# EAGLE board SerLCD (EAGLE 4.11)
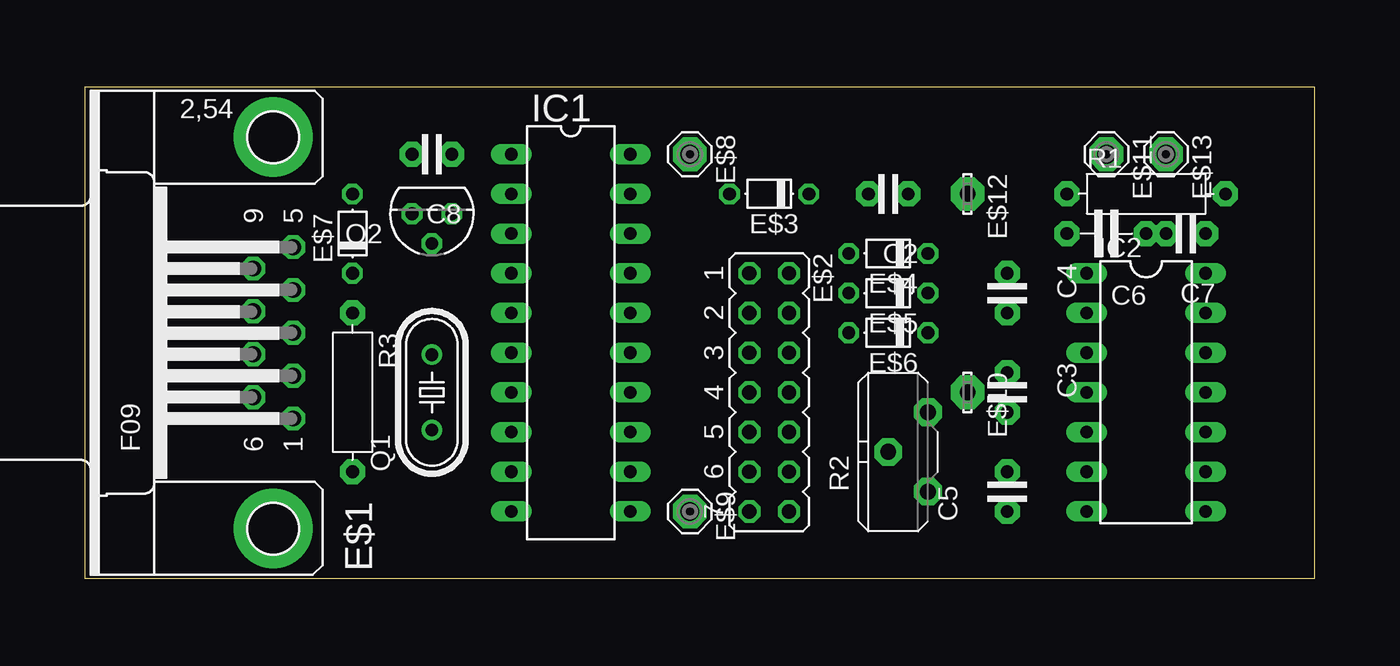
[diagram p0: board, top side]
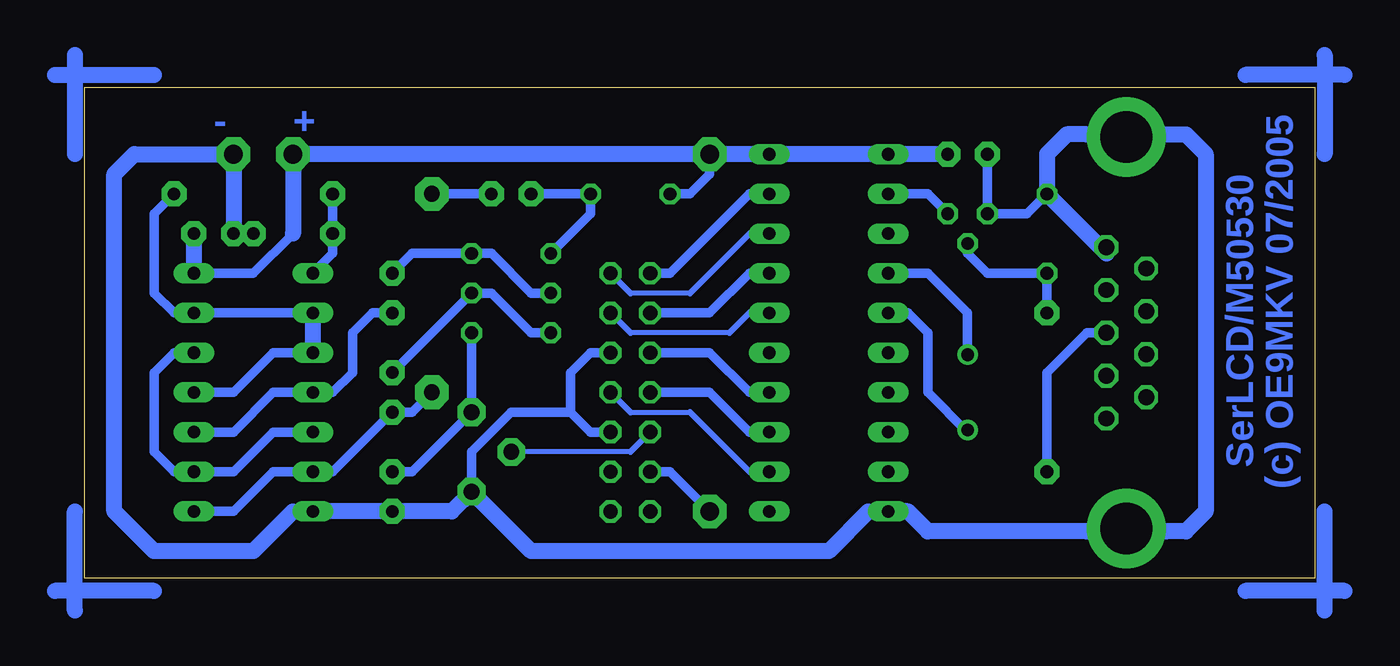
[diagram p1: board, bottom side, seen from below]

Size 78.73 x 31.42 mm. Coordinates in mm from the lower left corner, seen from the top.
Outline: 0,31.42 0,0 78.73,0 78.73,31.42 0,31.42
Copper layers (1*16): Top 0.035mm / dielectric 1.5mm / Bottom 0.035mm
Design rules "default": minimum track width 10mil, minimum drill 24mil, track to track 8mil, track to pad 8mil, pad to pad 8mil, via to via 8mil, smd to smd 8mil, copper to edge 40mil, drill to drill 8mil, minimum pad ring 10mil, minimum via ring 8mil, stop-mask expansion 4mil, vias tented up to drill 0mil, thermal gap 10mil

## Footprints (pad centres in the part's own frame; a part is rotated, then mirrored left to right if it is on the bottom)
C-2,5 = drill 0.813 pad 1.6 octagon: 1 -1.27,0; 2 1.27,0
C-5 = drill 0.813 pad 1.6 octagon: 1 -2.54,0; 2 2.54,0
F09HP = drill 1.016 octagon: 1 -5.486,-1.27; 2 -2.743,-1.27; 3 0,-1.27; 4 2.743,-1.27; 5 5.486,-1.27; 6 -4.115,1.27; 7 -1.372,1.27; 8 1.372,1.27; 9 4.115,1.27 | drill 3.302 pad 5.08 round: G1 -12.522,0; G2 12.522,0
JP7Q = drill 0.914 octagon: 1 -7.62,-1.27; 2 -7.62,1.27; 3 -5.08,-1.27; 4 -5.08,1.27; 5 -2.54,-1.27; 6 -2.54,1.27; 7 0,-1.27; 8 0,1.27; 9 2.54,-1.27; 10 2.54,1.27; 11 5.08,-1.27; 12 5.08,1.27; 13 7.62,-1.27; 14 7.62,1.27
D-5 = drill 0.813 octagon: A 2.54,0; C -2.54,0
MCS08 = drill 1.194 pad 2.159 octagon: MP 0,0
LSP10 = drill 1.016 pad 2.159 octagon: MP 0,0
DIL20 = drill 0.813 long: 1 -11.43,-3.81; 2 -8.89,-3.81; 3 -6.35,-3.81; 4 -3.81,-3.81; 5 -1.27,-3.81; 6 1.27,-3.81; 7 3.81,-3.81; 8 6.35,-3.81; 9 8.89,-3.81; 10 11.43,-3.81; 11 11.43,3.81; 12 8.89,3.81; 13 6.35,3.81; 14 3.81,3.81; 15 1.27,3.81; 16 -1.27,3.81; 17 -3.81,3.81; 18 -6.35,3.81; 19 -8.89,3.81; 20 -11.43,3.81
DIL14 = drill 0.813 long: 1 -7.62,-3.81; 2 -5.08,-3.81; 3 -2.54,-3.81; 4 0,-3.81; 5 2.54,-3.81; 6 5.08,-3.81; 7 7.62,-3.81; 8 7.62,3.81; 9 5.08,3.81; 10 2.54,3.81; 11 0,3.81; 12 -2.54,3.81; 13 -5.08,3.81; 14 -7.62,3.81
HC49/S = drill 0.813 round: 1 -2.413,0; 2 2.413,0
TO92 = drill 0.813 octagon: 1 1.27,0; 2 0,1.905; 3 -1.27,0
R-10 = drill 0.813 pad 1.6 octagon: 1 -5.08,0; 2 5.08,0
PT-10S = drill 1.016 pad 1.778 octagon: 1 -2.54,-1.27; 2 2.54,-1.27; 3 0,1.27

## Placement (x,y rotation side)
C2  10µ/16V  [C-2,5]  51.43,24.6 180 top
C3  10µ/16V  [C-2,5]  59.05,11.9 270 top
C4  10µ/16V  [C-2,5]  59.05,18.25 270 top
C5  22µ/35V  [C-2,5]  59.05,5.55 90 top
C6  1n  [C-5]  65.4,22.06 180 top
C7  100n  [C-2,5]  70.48,22.06 180 top
C8  100n  [C-2,5]  22.22,27.14 180 top
E$1  [F09HP]  12.06,15.71 90 top
E$2  [JP7Q]  43.81,11.9 270 top
E$3  [D-5]  43.81,24.6 180 top
E$4  [D-5]  51.43,20.79 180 top
E$5  [D-5]  51.43,18.25 180 top
E$6  [D-5]  51.43,15.71 180 top
E$7  [D-5]  17.14,22.06 90 top
E$8  [MCS08]  38.73,27.14 270 top
E$9  [MCS08]  38.73,4.28 270 top
E$10  [LSP10]  56.51,11.9 270 top
E$11  [MCS08]  65.4,27.14 270 top
E$12  [LSP10]  56.51,24.6 270 top
E$13  [MCS08]  69.21,27.14 270 top
IC1  AT90S2313P  [DIL20]  31.11,15.71 270 top
IC2  74HC14  [DIL14]  67.94,11.9 270 top
Q1  3.579545 MHz  [HC49/S]  22.22,11.9 90 top
Q2  BC547  [TO92]  22.22,23.33 180 top
R1  6k8  [R-10]  67.94,24.6 0 top
R2  10k  [PT-10S]  52.7,8.09 90 top
R3  10k  [R-10]  17.14,11.9 270 top

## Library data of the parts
C2-C8 R1-R3 = discrete
E$1 = con-subd
E$2 = jumper
E$3-E$7 = diode
E$8-E$13 = solpad
IC1 = atmel
IC2 = 74xx-eu
Q1 = crystal
Q2 = transistor-npn

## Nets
GND: C7.2 E$2.10 IC2.7
N$8: IC2.2 IC2.3 IC2.11 IC2.13
N$19: R2.1
N$23: C7.1 C8.1 E$3.A IC1.1 IC1.20 IC2.14
N$25: IC1.19
N$26: IC1.18
N$27: IC1.17
N$28: IC1.16
N$29: IC1.14
N$30: IC1.13
N$31: IC1.12
N$32: R2.3
N$35: R3.1
S$1: R3.2
S$2: E$1.3
S$3: Q2.3
S$5: IC2.6 IC2.8
S$6: E$2.1
S$7: E$2.3
S$8: E$2.2
S$9: E$2.4
S$10: E$2.7
S$12: E$2.8
S$14: C2.1
S$15: E$2.9
S$16: E$2.11 E$9.MP
S$18: Q2.1
S$19: E$2.6
S$21: IC2.4 IC2.10
S$24: IC2.5 IC2.9 IC2.12
S$27: C2.2 E$3.C E$4.A
S$29: IC1.4
S$30: IC1.5
S$31: R1.1
S$32: E$5.C E$6.A
S$33: C5.2 E$6.C R2.2
S$34: C4.2
S$35: C3.2 E$10.MP
S$36: E$4.C E$5.A
S$37: C4.1

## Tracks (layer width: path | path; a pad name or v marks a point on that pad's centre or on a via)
GND
  Bottom 0.61: E$2.10 46.35,9.36 47.62,10.63 | 47.62,10.63 47.62,11.9 | IC2.7 65.4,4.28 | 47.62,10.63 51.43,10.63 53.97,8.09 53.97,5.55 | 27.3,4.28 28.57,4.28
  Bottom 1.016: 65.4,4.28 67.94,1.74 74.29,1.74 76.83,4.28 76.83,25.87 75.56,27.14 69.21,27.14 C7.2 | IC2.7 55.24,4.28 53.97,5.55 50.16,1.74 31.11,1.74 28.57,4.28 | 27.3,4.28 26.03,4.28 24.76,3.01 14.6,3.01
N$8
  Bottom 0.61: IC2.11 69.21,11.9 66.67,14.44 IC2.3 | 73.02,24.6 74.29,23.33 74.29,18.25 73.02,16.98 IC2.13 IC2.2
  Bottom 1.016: IC2.2 IC2.3
N$23
  Bottom 0.61: 65.4,22.06 67.94,19.52 IC2.14 | 38.73,27.14 38.73,25.87 40,24.6 E$3.A
  Bottom 1.016: 65.4,22.06 65.4,27.14 38.73,27.14 IC1.20 IC1.1 C8.1 | C7.1 IC2.14
N$35
  Bottom 0.61: 22.22,20.79 20.95,19.52 17.14,19.52 R3.1
S$1
  Bottom 0.61: 17.14,13.17 R3.2
S$2
  Bottom 0.61: E$1.3 14.6,15.71 17.14,13.17
S$3
  Bottom 0.61: 26.03,24.6 24.76,24.6 Q2.3
S$4
  Bottom 1.016: 13.33,20.79 17.14,24.6
S$5
  Bottom 0.61: IC2.6 66.67,6.82 69.21,4.28 IC2.8
S$6
  Bottom 0.61: E$2.1 41.27,19.52 36.19,24.6 34.92,24.6
S$7
  Bottom 0.61: E$2.3 38.73,16.98 36.19,19.52 34.92,19.52
S$8
  Bottom 0.305: 40,18.25 43.81,18.25
  Bottom 0.406: 43.81,18.25 E$2.2 | 34.92,22.06 36.19,22.06 40,18.25
S$9
  Bottom 0.305: 37.46,15.71 43.81,15.71
  Bottom 0.406: 43.81,15.71 E$2.4 | 34.92,16.98 36.19,16.98 37.46,15.71
S$10
  Bottom 0.61: E$2.7 38.73,11.9 36.19,9.36 34.92,9.36
S$11
  Bottom 1.016: 9.52,28.41 8.25,28.41 6.98,27.14 6.98,4.28 8.25,3.01 9.52,3.01
S$12
  Bottom 0.305: 43.81,10.63 40,10.63
  Bottom 0.406: E$2.8 43.81,10.63 | 40,10.63 36.19,6.82 34.92,6.82
S$13
  Bottom 0.61: 42.54,14.44 38.73,14.44 36.19,11.9 34.92,11.9
S$14
  Bottom 0.61: C2.1 56.51,24.6
S$15
  Bottom 0.305: 43.81,8.09 51.43,8.09
  Bottom 0.406: E$2.9 43.81,8.09
S$16
  Bottom 0.61: E$2.11 41.27,6.82 E$9.MP
S$17
  Bottom 1.016: -0.64,33.49 -0.64,27.14
S$18
  Bottom 0.61: 20.95,27.14 Q2.1 18.41,23.33 17.14,24.6
S$19
  Bottom 0.61: 47.62,11.9 47.62,13.17 46.35,14.44 E$2.6
S$20
  Bottom 1.016: -1.91,32.22 4.44,32.22
S$21
  Bottom 0.61: IC2.4 66.67,11.9 69.21,9.36 IC2.10
S$22
  Bottom 1.016: -0.64,-2.07 -0.64,4.28
S$23
  Bottom 1.016: -1.91,-0.8 4.44,-0.8
S$24
  Bottom 0.61: IC2.12 73.02,14.44 74.29,13.17 74.29,8.09 73.02,6.82 IC2.9 69.21,6.82 66.67,9.36 IC2.5
S$25
  Bottom 1.016: 74.29,-0.8 80.64,-0.8
S$26
  Bottom 0.61: 53.97,18.25 59.05,13.17
S$27
  Bottom 0.61: E$4.A 46.35,23.33 E$3.C C2.2
S$28
  Bottom 1.016: 17.14,24.6 17.14,27.14 15.87,28.41 14.6,28.41
S$29
  Bottom 0.61: IC1.4 24.76,19.52 22.22,16.98 22.22,14.44
S$30
  Bottom 0.61: IC1.5 26.03,16.98 24.76,15.71 24.76,11.9 22.22,9.36
S$31
  Bottom 0.61: R1.1 62.86,20.79 64.13,19.52
S$32
  Bottom 0.61: E$5.C 52.7,18.25 50.16,15.71 E$6.A
S$33
  Bottom 0.61: C5.2 57.78,6.82 R2.2 E$6.C
S$34
  Bottom 0.61: C4.2 60.32,16.98 61.59,15.71 61.59,13.17 62.86,11.9
S$35
  Bottom 0.61: 62.86,6.82 C3.2 57.78,10.63 E$10.MP
S$36
  Bottom 0.61: E$4.C 52.7,20.79 50.16,18.25 E$5.A
S$37
  Bottom 0.61: 53.97,20.79 57.78,20.79 C4.1
S$38
  Bottom 1.016: 79.37,-2.07 79.37,4.28
S$39
  Bottom 1.016: 79.37,33.49 79.37,27.14
S$40
  Bottom 1.016: 80.64,32.22 74.29,32.22

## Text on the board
Bottom: (c) OE9MKV 07/2005 | + | - | SerLCD/M50530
